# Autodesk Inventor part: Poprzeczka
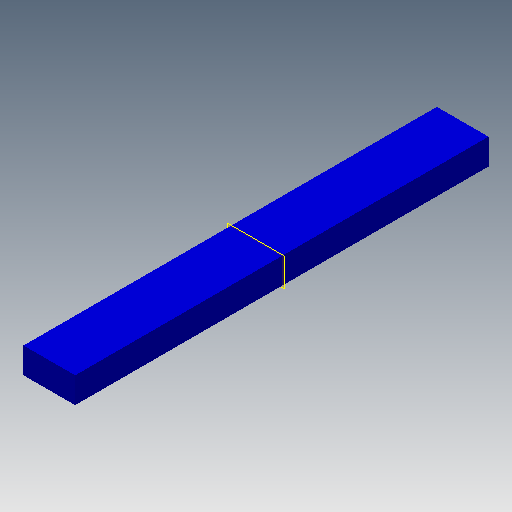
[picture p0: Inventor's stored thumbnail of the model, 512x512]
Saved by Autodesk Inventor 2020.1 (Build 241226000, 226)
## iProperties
Created: 2005-09
Part Number: Poprzeczka
Document SubType Name: Modeling
Description: Poprzeczka
Density: 1 g/cm^3
Material: Ogólny
Appearance: Niebieski
Designer: F.Stasiak
Manager: www.cadconsulting.pl
Company: Fabian Stasiak CAD Consulting
Author: F.Stasiak
Subject: Zbiór ćwiczeń. Autodesk Inventor 2020. Kurs podstawowy
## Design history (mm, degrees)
sketch "Szkic1"
  geometry: L1 (-58.533, 71.321)-(41.467, 71.321); L2 (41.467, 71.321)-(41.467, 21.321); L3 (41.467, 21.321)-(-58.533, 21.321); L4 (-58.533, 21.321)-(-58.533, 71.321)
  constraints: 8 end point, 2 parallel, 1 horizontal, 1 perpendicular
  dimensions: "d0" = 50 distance of L3.end L1.start; "d1" = 100 distance of L1.start L1.end
extrude "Wyciągnięcie proste1" new body sketch "Szkic1" distance "d2" = 800; taper "d3" = 0 deg
feature "Skorupa1" dims "d5" = 15
node "Płaszczyzna konstrukcyjna1"
node "Bryła1"
node "Korpusy bryłowe"
node "Korpusy powierzchniowe"
